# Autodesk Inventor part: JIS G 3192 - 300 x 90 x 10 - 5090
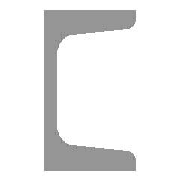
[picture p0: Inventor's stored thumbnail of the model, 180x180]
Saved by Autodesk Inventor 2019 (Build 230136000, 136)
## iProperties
_CCFamilyMember: 12
_CCFamilyDisplayName: JIS G 3192 - U 形熱間圧延鋼
_FrameMemberDoc: Frame Member File
_Version: 15.0.0
_GetPNFromCC: 1
Created: 2017-02
Part Number: JIS G 3192 - 300 x 90 x 10 - 5090
Material: 鋼、軟鋼
Description: U 形熱間圧延鋼
Document SubType Name: Modeling
Standard: JIS
Designer: shimont
Standard Revision: 2014
Standards Organization: JIS
Language: ja-JP
Size Designation: 300 x 90 x 10
Categories: <MemberInstance><Categories><Category DisplayName="形鋼" InternalName="089c4875-fa83-4c05-b084-43b9cc11f5ed" Mnemonic="GRDR"><CategoryParameter DisplayName="長さ単位ご
Stock Number: 300 x 90 x 10
Density: 7.85 g/cm^3
Appearance: 半つや出し
Mass: 95128.3 g
Surface Area: 19850.9 cm^2
Volume: 12118.3 cm^3
IsCustomPart: 1
G_W: 90.000 mm
G_H: 300.000 mm
G_L: 5090.000 mm
+3474794D-67EB-4315-BA13-F1D82DAACDBE+CUTDETAIL3: カット角度 90.00 deg
Author: shimont
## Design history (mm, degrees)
node "開始平面"
node "終了平面"
sketch "スケッチ"
  geometry: L1 (-23.4, 0)-(-23.4, 150); L2 (-23.4, 150)-(66.6, 150); L3 (66.6, 150)-(66.6, 146.705); L4 (57.928, 137.241)-(3.944, 132.518); L5 (-13.4, 113.59)-(-13.4, 0); L6 (-13.4, 0)-(-23.4, 0); L7 (26.6, 150)-(26.6, 134.5); L8 (66.6, 138)-(66.6, 134.5); L9 (66.6, 134.5)-(26.6, 134.5); L10 (0, 15)-(0, -27); L11 (-5.539, 0)-(16.007, 0); L12 (-23.4, 0)-(-23.4, -150); L13 (-23.4, -150)-(66.6, -150); L14 (66.6, -150)-(66.6, -146.705); L15 (57.928, -137.241)-(3.944, -132.518); L16 (-13.4, -113.59)-(-13.4, 0); L17 (0, 210)-(0, -210) reference; L18 (-41.768, 0)-(86.808, 0) reference; A1 r 19 centre (5.6, 113.59) between (3.944, 132.518) and (-13.4, 113.59); A2 r 19 centre (5.6, -113.59) between (-13.4, -113.59) and (3.944, -132.518); A3 r 9.5 centre (57.1, 146.705) between (57.928, 137.241) and (66.6, 146.705); A4 r 9.5 centre (57.1, -146.705) between (66.6, -146.705) and (57.928, -137.241); 5 further points
  constraints: 32 end point, 12 point on line, 8 point on circle, 8 tangent, 6 symmetric about line, 4 centre point, 4 parallel, 3 collinear, 3 perpendicular, 2 equal radius, 5 other
  dimensions: "d0" = 10 distance between parallel lines of L1 L5 (= G_T); "d1" = 150 distance between parallel lines of L6 L2 (= 0.5 x G_H); "d2" = 90 distance between parallel lines of L3 L1 (= G_W); "d3" = 15.5 distance of L2.end L8.end (= G_T1); "d4" = 40 distance of L7.start L2.end (= G_C); "d5" = 3.4996 distance of L8.start L8.end (computed from G_NG, G_C); "d23" = 19 radius of A1 (= G_IR); "d24" = 9.5 radius of A3 (= G_ER); "d25" = 23.4 distance between parallel lines of L10 L12 (= ey)
extrude "ボディ" new body sketch "スケッチ" stored distance "d6" = 5090 (= G_L); taper "d7" = 0 deg
node "Driven Length"
  sketch "Sketch3"
    geometry: L1 (0, 0)-(10, 0) reference
    constraints: 2 end point, 1 horizontal
  workplane "Work Plane3"
  sketch "Sketch4"
    geometry: L1 (-2, -90)-(12, -90) reference; L2 (-2, 2090)-(12, 2090) reference
    dimensions: "d29" = 2180 distance between parallel lines of L1 L2 (derived)
node "作業平面4"
feature "分割1"
node "作業平面9"
feature "分割6"
node "穴2"
body "Solid1"
sketch "スケッチ5"
  geometry: 4 further points
hole "穴1" sketch "スケッチ5" diameter "d30" = 33; stored, may be unused: countersink angle "d34" = 90 deg, drill point angle "d36" = 0 deg; dims "d31" = 6, "d32" = 4, "d33" = 2, "d35" = 8
other parameters: "G_W" = 90 [user parameter; used in 1 equation term], "G_H" = 300 [user parameter; used in 1 equation term], "G_T" = 10 [user parameter; used in 1 equation term], "G_T1" = 15.5 [user parameter; used in 1 equation term], "G_NG" = 0.8749 [user parameter; used in 1 equation term], "G_ER" = 9.5 [user parameter; used in 1 equation term], "G_IR" = 19 [user parameter; used in 1 equation term], "G_C" = 40 [user parameter; used in 2 equation terms], "G_L" = 5090 [user parameter; used in 1 equation term], "ey" = 23.4 [user parameter; used in 1 equation term], "d28" = 90 deg
